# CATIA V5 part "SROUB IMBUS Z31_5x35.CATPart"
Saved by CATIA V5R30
Part number: SROUB IMBUS Z31/5x35
Bounding box of the stored display mesh (mm): x -5 to 35, y -4.24 to 4.24, z -4.25 to 4.25
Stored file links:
  C:\Users\ondra\Desktop\PŘÍLOHA P III\CATIA\SROUB IMBUS Z31_5x35.CATPart
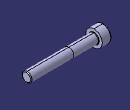
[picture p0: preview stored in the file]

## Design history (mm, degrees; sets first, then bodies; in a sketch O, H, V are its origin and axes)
Set1
  DatumSurface1 to DatumSurface29 "Z31/5x35"
  Join1: Elements (DatumSurface1; DatumSurface2; DatumSurface3; DatumSurface4; DatumSurface5; DatumSurface6; DatumSurface7; DatumSurface8; DatumSurface9; DatumSurface10; DatumSurface11; DatumSurface12; DatumSurface13; DatumSurface14; DatumSurface15; DatumSurface16; DatumSurface17; DatumSurface18; DatumSurface19; DatumSurface20; DatumSurface21; DatumSurface22; DatumSurface23; DatumSurface24; DatumSurface25; DatumSurface26; DatumSurface27; DatumSurface28; DatumSurface29)
Set2 "Geometry Failure"
  Set3 "FaceKO#Z31/5x35#409"
    DatumSurface30 "Sur409_1"
    Circle1 "Crv409_1": stored without definition
    DatumCurve1 "PCrv409_1"
    Circle2 "Crv409_2": stored without definition
    DatumCurve2 "PCrv409_2"
    Circle3 "Crv409_3": stored without definition
    DatumCurve3 "PCrv409_3"
    Circle4 "Crv409_4": stored without definition
    DatumCurve4 "PCrv409_4"
Body1 (main body)
  CloseSurface1: CloseElement Join1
